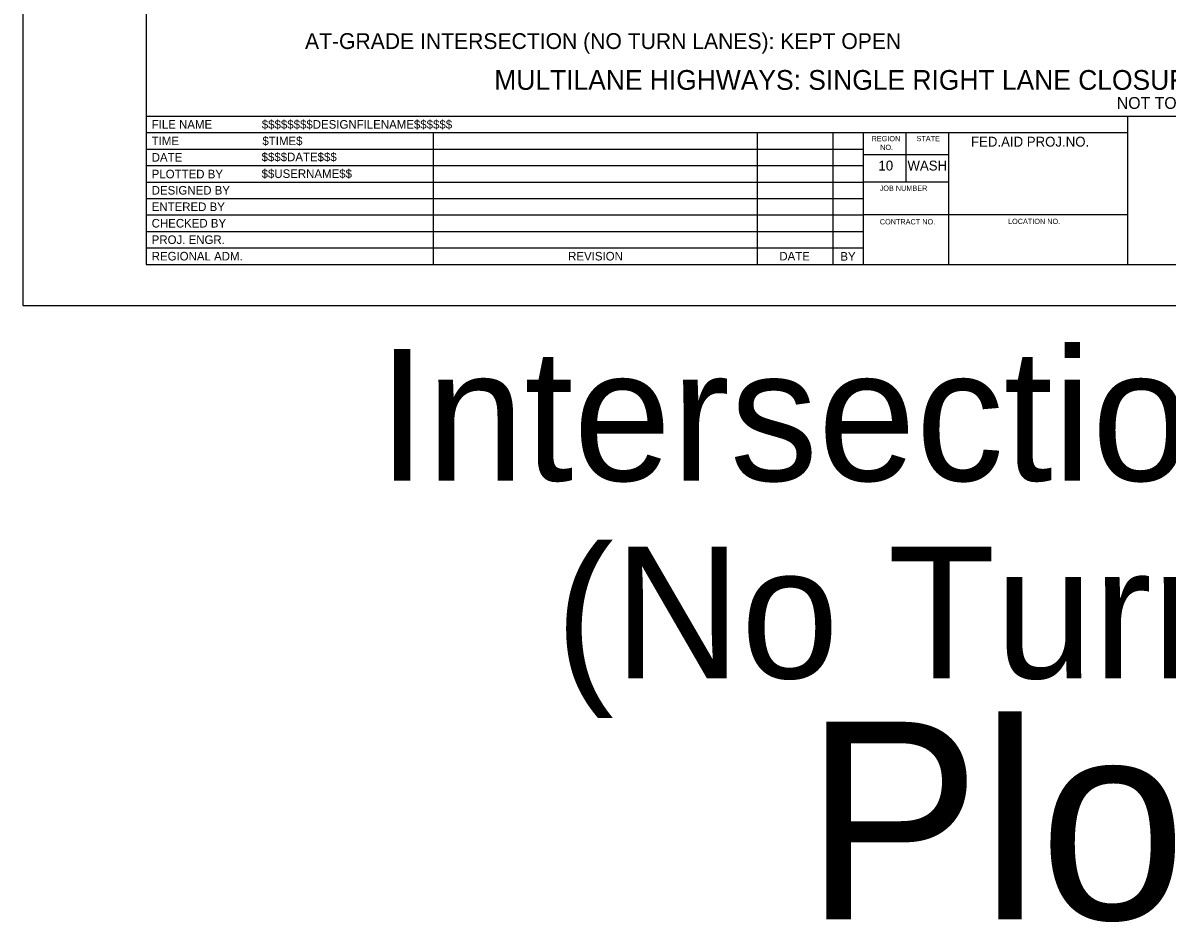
# Model space of a CAD drawing. Extents: x 99958 to 100176, y 99935 to 100011.
# Drawn here: x 100039.06 to 100047.76, y 99995.01 to 100001.83 of the extents above; entities that cross this region are included whole.
import ezdxf

# ---------------------------------------------------------------- set-up
doc = ezdxf.new("R2010")
doc.units = 0
for name, color, linetype in [('SH_DE_DetailHeading1Text', 7, 'Continuous'), ('SH_DE_DetailHeading2Text', 7, 'Continuous'), ('SH_GI_PlotLimits', 7, 'Continuous'), ('SH_GI_SheetBorder', 7, 'Continuous'), ('SH_GI_SheetLocationText', 7, 'Continuous'), ('SH_GI_SheetTextInCells', 7, 'Continuous'), ('SH_GI_TitleBlockText', 7, 'Continuous')]:
    doc.layers.add(name, color=color, linetype=linetype)

msp = doc.modelspace()

# ---------------------------------------------------------------- linework, layer by layer
at = {"layer": 'SH_GI_PlotLimits'}
msp.add_lwpolyline([(100039.0625, 99999.6875), (100056.0625, 99999.6875), (100056.0625, 100010.6875), (100039.0625, 100010.6875)], close=True, dxfattribs=at)
at = {"layer": 'SH_GI_SheetBorder'}
for p, q in [((100040, 100010.375), (100040, 100000)), ((100040, 100001.1259), (100055.75, 100001.1259)), ((100047.4566, 100000), (100047.4566, 100001.1259)), ((100040, 100001.0008), (100047.4566, 100001.0008)), ((100042.179, 100001.0008), (100042.179, 100000)), ((100044.641, 100001.0008), (100044.641, 100000)), ((100045.2164, 100001.0008), (100045.2164, 100000)), ((100045.4451, 100001.0008), (100045.4451, 100000)), ((100045.7719, 100000.6255), (100045.7719, 100001.0008)), ((100046.0956, 100000), (100046.0956, 100001.0008)), ((100040, 100000.8757), (100042.1821, 100000.8757)), ((100042.1821, 100000.8757), (100045.4466, 100000.8757)), ((100046.0958, 100000.831), (100045.4466, 100000.831)), ((100040, 100000.7506), (100042.1821, 100000.7506)), ((100042.1821, 100000.7506), (100045.4466, 100000.7506)), ((100040, 100000.6255), (100045.4466, 100000.6255)), ((100046.0958, 100000.6255), (100045.4466, 100000.6255)), ((100040, 100000.5004), (100045.4466, 100000.5004)), ((100040, 100000.3753), (100045.4466, 100000.3753)), ((100047.4566, 100000.3753), (100045.4466, 100000.3753)), ((100040, 100000.2502), (100045.4466, 100000.2502)), ((100040, 100000.1251), (100045.4466, 100000.1251)), ((100040, 100000), (100055.75, 100000))]:
    msp.add_line(p, q, dxfattribs=at)

# ---------------------------------------------------------------- texts
at = {"layer": 'SH_DE_DetailHeading1Text'}
for s, height, p in [('MULTILANE HIGHWAYS: SINGLE RIGHT LANE CLOSURE (45+ MPH, MAINTAIN EXISTING SPEED LIMIT)', 0.15, (100042.6439, 100001.3259)), ('NOT TO SCALE', 0.09, (100047.3727, 100001.1809))]:
    msp.add_text(s, height=height, rotation=360, dxfattribs=at).set_placement(p)
at = {"layer": 'SH_DE_DetailHeading2Text'}
msp.add_text('AT-GRADE INTERSECTION (NO TURN LANES): KEPT OPEN', height=0.12, rotation=360, dxfattribs=at).set_placement((100041.2057, 100001.6359))
at = {"layer": 'SH_GI_SheetLocationText'}
for s, height, p in [('Intersections, ML Hwy', 1, (100041.7579, 99998.3571)), ('(No Turn Lanes)', 1, (100043.1065, 99996.8571)), ('Plot 3', 1.5, (100045.0008, 99995.0267))]:
    msp.add_text(s, height=height, dxfattribs=at).set_placement(p)
at = {"layer": 'SH_GI_SheetTextInCells'}
for s, height, p in [('FILE NAME', 0.06505, (100040.041, 100001.0308)), ('TIME', 0.06505, (100040.041, 100000.9057)), ('REGION', 0.04003, (100045.5099, 100000.9352)), ('STATE', 0.04003, (100045.8511, 100000.9357)), ('FED.AID PROJ.NO.', 0.07506, (100046.2652, 100000.8945)), ('NO.', 0.04003, (100045.5752, 100000.869)), ('DATE', 0.06505, (100040.041, 100000.7806)), ('10', 0.07506, (100045.5621, 100000.7131)), ('WASH', 0.07506, (100045.7826, 100000.7131)), ('PLOTTED BY', 0.06505, (100040.041, 100000.6538)), ('DESIGNED BY', 0.065052, (100040.041, 100000.5304)), ('JOB NUMBER', 0.04003, (100045.5712, 100000.5587)), ('ENTERED BY', 0.06505, (100040.041, 100000.4053)), ('CHECKED BY', 0.06505, (100040.041, 100000.2802)), ('LOCATION NO.', 0.040032, (100046.5465, 100000.3067)), ('CONTRACT NO.', 0.040032, (100045.5725, 100000.3037)), ('PROJ. ENGR.', 0.065052, (100040.041, 100000.1551)), ('REGIONAL ADM.', 0.065052, (100040.041, 100000.03)), ('REVISION', 0.06505, (100043.2048, 100000.03)), ('DATE', 0.06505, (100044.8091, 100000.03)), ('BY', 0.06505, (100045.2725, 100000.0285))]:
    msp.add_text(s, height=height, dxfattribs=at).set_placement(p)
at = {"layer": 'SH_GI_TitleBlockText'}
for s, height, p in [('$$$$$$$$DESIGNFILENAME$$$$$$', 0.065052, (100040.8775, 100001.0308)), ('$TIME$', 0.06505, (100040.882, 100000.9059)), ('$$$$DATE$$$', 0.065052, (100040.8759, 100000.7835)), ('$$USERNAME$$', 0.065052, (100040.8759, 100000.6567))]:
    msp.add_text(s, height=height, dxfattribs=at).set_placement(p)

doc.saveas('drawing.dxf')
